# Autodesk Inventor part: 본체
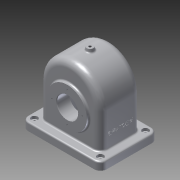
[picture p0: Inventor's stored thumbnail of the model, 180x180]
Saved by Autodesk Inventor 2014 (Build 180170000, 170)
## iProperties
Created: 2016-10
Part Number: 본체
Material: 알루미늄 6061
Document SubType Name: Modeling
Designer: a
Density: 2.71 g/cm^3
Appearance: 알루미늄 - 평지
Mass: 1261.07 g
Surface Area: 1205.98 cm^2
Volume: 465.341 cm^3
Author: a
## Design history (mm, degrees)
sketch "스케치1"
  geometry: L1 (110, 15)-(0, 15); L2 (0, 15)-(0, 0); L3 (0, 0)-(110, 0); L4 (110, 0)-(110, 15)
  constraints: 8 end point, 2 parallel, 1 horizontal, 1 perpendicular
  dimensions: "d0" = 15 distance of L1.end L2.end; "d1" = 110 distance of L1.start L1.end
extrude "돌출1" new body sketch "스케치1" distance "d2" = 150; taper "d3" = 0 deg
node "작업 평면1"
sketch "스케치2"
  geometry: L1 (0, 0)-(-150, 0) reference; L2 (-150, 0)-(-150, 15) reference; L3 (-150, 15)-(0, 15) reference; L4 (0, 15)-(0, 0) reference; L5 (-133, 15)-(-133, 138); L6 (-133, 138)-(-17, 138); L7 (-17, 138)-(-17, 15); 2 further points
  constraints: 6 end point, 2 midpoint, 2 perpendicular, 2 point on line, 1 parallel, 1 vertical alignment
  dimensions: "d4" = 116 distance of L5.end L6.end; "d20" = 123 distance of L5.start L5.end
extrude "돌출2" join sketch "스케치2" stored distance "d5" = 77; taper "d6" = 0 deg
fillet "모깎기1" dims "d7" = 58
sketch "스케치3"
  geometry: L1 (0, 0)-(-150, 0) reference; C1 r 31 at (-75, 65)
  constraints: 1 centre point
  dimensions: "d8" = 62 diameter of C1; "d21" = 65 distance from line of L1 C1.centre
extrude "돌출3" join sketch "스케치3" distance "d10" = 10; taper "d11" = 0 deg
node "작업 평면2"
sketch "스케치4"
  geometry: L1 (0, 0)-(-150, 0) reference; L2 (-150, 0)-(-150, 15) reference; L3 (-150, 15)-(-133, 15) reference; L4 (-133, 15)-(-133, 80) reference; L5 (-17, 80)-(-17, 15) reference; L6 (-17, 15)-(0, 15) reference; L7 (0, 15)-(0, 0) reference; L8 (-127, 80)-(-127, 0); L9 (-23, 80)-(-23, 0); A1 r 58 centre (-75, 80) between (-17, 80) and (-133, 80) reference; A2 r 52 centre (-75, 80) between (-23, 80) and (-127, 80)
  constraints: 4 end point, 2 perpendicular, 2 point on circle, 2 point on line, 2 tangent, 1 centre point, 1 coincident
  dimensions: "d12" = 104 diameter of A2
extrude "돌출4" cut sketch "스케치4" stored distance "d13" = 67; taper "d14" = 0 deg
sketch "스케치5"
  geometry: L1 (0, 0)-(0, 123) reference; L2 (0, 123)-(77, 123) reference; L3 (77, 123)-(77, 81) reference; L4 (77, 81)-(87, 81) reference; L5 (87, 81)-(87, 19) reference; L6 (87, 19)-(77, 19) reference; L7 (77, 19)-(77, 0) reference; L8 (77, 0)-(93.5, 0) reference; L9 (93.5, 0)-(93.5, -15) reference; L10 (93.5, -15)-(72, -15) reference; L11 (72, -15)-(72, 117) reference; L12 (72, 117)-(5, 117) reference; L13 (5, 117)-(5, -15) reference; L14 (5, -15)-(-16.5, -15) reference; L15 (-16.5, -15)-(-16.5, 0) reference; L16 (-16.5, 0)-(0, 0) reference; L17 (5, 89.747)-(19, 78); L18 (19, 78)-(19, 22); L19 (19, 22)-(5, 10.253); L20 (0, 87.5)-(-5, 87.5); L21 (-5, 87.5)-(-5, 12.5); L22 (-5, 12.5)-(0, 12.5); L23 (-5, 50)-(19, 50); L24 (5, 89.747)-(0, 93.943); 1 further point
  constraints: 16 end point, 5 point on line, 4 perpendicular, 3 midpoint, 2 horizontal alignment, 1 collinear, 1 equal length, 1 parallel
  dimensions: "d15" = 56 distance of L17.end L18.end; "d16" = 50 deg angle of L18 L17; "d17" = 75 distance of L20.end L21.end; "d18" = 5 distance of L20.start L20.end; "d79" = 24 distance between parallel lines of L18 L21
revolve "회전1" sketch "스케치5" stored, may be unused: angle "d19" = 90 deg
fillet "모깎기2" dims "d22" = 13
fillet "모깎기3" dims "d23" = 8
fillet "모깎기4" dims "d24" = 12
sketch "스케치6"
  geometry: C1 r 37.5 at (0, 0) reference; C2 r 20 at (0, 0); 1 further point
  constraints: 1 centre point, 1 coincident
  dimensions: "d25" = 40 diameter of C2
extrude "돌출5" cut sketch "스케치6" stored distance "d26" = 67; taper "d27" = 0 deg
chamfer "모따기1" distance "d28" = 1; stored, may be unused: second distance "d29" = 2, angle "d30" = 45 deg
fillet "모깎기5" dims "d31" = 3
sketch "스케치7"
  geometry: C1 r 37.5 at (0, 0) reference; 2 further points
  dimensions: "d32" = 29 distance of point (0, 29) C1.centre
hole "구멍1" sketch "스케치7" at (0, 29) diameter "d33" = 2.459; stored, may be unused: countersink angle "d37" = 90 deg, drill point angle "d39" = 118 deg; dims "d34" = 6, "d35" = 4, "d36" = 2, "d38" = 8
node "작업축1"
sketch "스케치8"
  geometry: C1 r 31 at (0, 0) reference; 2 further points
  dimensions: "d43" = 26 distance of point (0, 26) C1.centre
hole "구멍2" sketch "스케치8" at (0, 26) diameter "d44" = 2.459; stored, may be unused: countersink angle "d48" = 90 deg, drill point angle "d50" = 118 deg; dims "d45" = 6, "d46" = 4, "d47" = 2, "d49" = 8
node "작업 평면4"
  node "작업 평면3"
fillet "모깎기7" dims "d66" = 3
sketch "스케치11"
  geometry: L1 (-17.5, -80)-(68.5, -80) reference; L2 (-13, 0)-(-13, -62) reference; 2 further points
  constraints: 1 other
  dimensions: "d67" = 40 distance from line of L1 point (25.5, -40); "d68" = 38.5 distance from line of point (25.5, -40) L2
feature "엠보싱1" sketch "스케치11" dims "d0" = 15, "d1" = 110, "d69" = 0.5, "d70" = 0
sketch "스케치12"
  geometry: A1 r 9 centre (86, -135) between (86, -144) and (95, -135) reference; A2 r 9 centre (86, -9) between (95, -9) and (86, 0) reference; A3 r 9 centre (0, -9) between (0, 0) and (-9, -9) reference; A4 r 9 centre (0, -135) between (-9, -135) and (0, -144) reference; 1 further point
hole "구멍4" sketch "스케치12" at (0, -9), (86, -9), (86, -135), (0, -135) diameter "d71" = 5; stored, may be unused: countersink angle "d75" = 90 deg, drill point angle "d77" = 118 deg; dims "d72" = 20, "d73" = 12, "d74" = 5, "d76" = 20
fillet "모깎기8" dims "d78" = 3
sketch "스케치13"
  geometry: L1 (86, 30)-(87, 29) reference; L2 (87, 29)-(87, 25.23) reference; L3 (87, 25.23)-(79, 25.23) reference; L4 (79, 25.23)-(78.261, 24) reference; L5 (78.261, 24)-(79, 22.771) reference; L6 (79, 22.771)-(87, 22.771) reference; L7 (87, 22.771)-(87, 19) reference; L8 (87, 19)-(80, 19) reference; L9 (77, 16)-(77, 3) reference; L10 (80, 0)-(90.5, 0) reference; L11 (93.5, -3)-(93.5, -15) reference; L12 (93.5, -15)-(72, -15) reference; L13 (72, -15)-(72, 30) reference; L14 (72, 30)-(86, 30) reference; L15 (-5, 29)-(-4, 30) reference; L16 (-4, 30)-(19, 30) reference; L17 (19, 30)-(19, 22) reference; L18 (19, 22)-(6.072, 11.152) reference; L19 (5, 8.854)-(5, -15) reference; L20 (5, -15)-(-16.5, -15) reference; L21 (-16.5, -15)-(-16.5, -3) reference; L22 (-13.5, 0)-(-3, 0) reference; L23 (0, 3)-(0, 9.5) reference; L24 (-3, 12.5)-(-5, 12.5) reference; L25 (-5, 12.5)-(-5, 19.771) reference; L26 (-5, 19.771)-(3, 19.771) reference; L27 (3, 19.771)-(3.739, 21) reference; L28 (3.739, 21)-(3, 22.23) reference; L29 (3, 22.23)-(-5, 22.23) reference; L30 (-5, 22.23)-(-5, 29) reference; L31 (64, 117)-(13, 117) reference; L32 (5, 109)-(5, 91.146) reference; L33 (6.072, 88.848)-(19, 78) reference; L34 (19, 78)-(19, 70) reference; L35 (19, 70)-(-4, 70) reference; L36 (-4, 70)-(-5, 71) reference; L37 (-5, 71)-(-5, 77.771) reference; L38 (-5, 77.771)-(3, 77.771) reference; L39 (3, 77.771)-(3.739, 79) reference; L40 (3.739, 79)-(3, 80.23) reference; L41 (3, 80.23)-(-5, 80.23) reference; L42 (-5, 80.23)-(-5, 87.5) reference; L43 (-5, 87.5)-(-3, 87.5) reference; L44 (0, 90.5)-(0, 110) reference; L45 (13, 123)-(64, 123) reference; L46 (77, 110)-(77, 84) reference; L47 (80, 81)-(87, 81) reference; L48 (87, 81)-(87, 77.23) reference; L49 (87, 77.23)-(79, 77.23) reference; L50 (79, 77.23)-(78.261, 76) reference; L51 (78.261, 76)-(79, 74.771) reference; L52 (79, 74.771)-(87, 74.771) reference; L53 (87, 74.771)-(87, 71) reference; L54 (87, 71)-(86, 70) reference; L55 (86, 70)-(72, 70) reference; L56 (72, 70)-(72, 109) reference; L57 (31.442, 123)-(32.5, 129); L58 (32.5, 129)-(44.5, 129); L59 (44.5, 129)-(45.558, 123); L60 (38.5, 123)-(38.5, 129); L61 (31.442, 123)-(30.771, 119.192); L62 (30.771, 119.192)-(46.229, 119.192); L63 (45.558, 123)-(46.229, 119.192); L64 (38.5, 123)-(38.5, 119.192); A1 r 3 centre (80, 16) between (80, 19) and (77, 16) reference; A2 r 3 centre (80, 3) between (77, 3) and (80, 0) reference; A3 r 3 centre (90.5, -3) between (93.5, -3) and (90.5, 0) reference; A4 r 3 centre (8, 8.854) between (6.072, 11.152) and (5, 8.854) reference; A5 r 3 centre (-13.5, -3) between (-13.5, 0) and (-16.5, -3) reference; A6 r 3 centre (-3, 3) between (-3, 0) and (0, 3) reference; A7 r 3 centre (-3, 9.5) between (0, 9.5) and (-3, 12.5) reference; A8 r 8 centre (64, 109) between (72, 109) and (64, 117) reference; A9 r 8 centre (13, 109) between (13, 117) and (5, 109) reference; A10 r 3 centre (8, 91.146) between (5, 91.146) and (6.072, 88.848) reference; A11 r 3 centre (-3, 90.5) between (-3, 87.5) and (0, 90.5) reference; A12 r 13 centre (13, 110) between (13, 123) and (0, 110) reference; A13 r 13 centre (64, 110) between (77, 110) and (64, 123) reference; A14 r 3 centre (80, 84) between (77, 84) and (80, 81) reference
  constraints: 16 end point, 3 midpoint, 3 perpendicular, 2 collinear, 2 point on line, 1 equal length, 1 vertical alignment
  dimensions: "d80" = 6 distance between parallel lines of L58 L45; "d81" = 100 deg angle of L45 L57; "d82" = 12 distance of L57.end L58.end
revolve "회전2" sketch "스케치13" stored, may be unused: angle "d83" = 90 deg
fillet "모깎기9" dims "d84" = 3
sketch "스케치14"
  geometry: C1 r 6 at (0, 0) reference; 1 further point
hole "구멍5" sketch "스케치14" at (0, 0) diameter "d85" = 4.459; stored, may be unused: countersink angle "d89" = 90 deg, drill point angle "d91" = 118 deg; dims "d86" = 20, "d87" = 12, "d88" = 5, "d90" = 20
node "솔리드1"
pattern_circular "원형 패턴1" dims angle "d41" = 360 deg
pattern_circular "원형 패턴2" dims angle "d52" = 360 deg
node "절단 모서리 투영1"
node "절단 모서리 투영2"
node "절단 모서리 투영3"
node "절단 모서리 투영4"
other parameters: "d54" = 6
